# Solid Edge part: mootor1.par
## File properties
Author: Priit
Template: Normal.par
Last saved by: Priit
Revision: 7
Application: Solid Edge
Accuracy: 0,990
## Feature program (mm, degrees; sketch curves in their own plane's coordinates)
sketch for "unnamed Protrusion 1" plane through (0, 0, 0) normal (0, -1, 0) x-axis (1, 0, 0)
  circle centre (0, 0) radius 20
extrude "unnamed Protrusion 1" add finite 10 along -normal
sketch for "ExtrudedCutout_1" plane through (0, 0, 0) normal (0, -1, 0) x-axis (1, 0, 0)
  circle centre (0, 0) radius 15
extrude "ExtrudedCutout_1" cut finite 10 along -normal
fillet "Round_1" radius 5
sketch for "ExtrudedProtrusion_2" plane through (0, 0, 0) normal (1, 0, 0) x-axis (0, 1, 0)
  bspline degree 3 poles (2.6212, 20) (4.3488, 21.4343) (6.0292, 21.9791) (7.6625, 21.6343) knots 0 1 multiplicities 4 4
  line (6.3474, 18.5657) -> (7.6625, 21.6343)
  line (2.1828, 18.5657) -> (6.3474, 18.5657)
  line (2.1828, 18.5657) -> (2.6212, 20)
extrude "ExtrudedProtrusion_2" add finite 1 symmetric
pattern "unnamed Pattern 1" of "ExtrudedProtrusion_2"
pattern "unnamed Pattern 2"
sketch for "unnamed RevolvedProtrusion 1" plane through (0, 0, 0) normal (1, 0, 0) x-axis (0, 1, 0)
  line (10, 20) -> (15, 25)
  line (15, 25) -> (15, 20)
  line (10, 16) -> (15, 20)
  line (10, 20) -> (10, 16)
revolve "unnamed RevolvedProtrusion 1" add finite 360 deg
fillet "Round_2" radius 1
sketch for "ExtrudedCutout_2" plane through (0, 0, 0) normal (0, -1, 0) x-axis (1, 0, 0)
  circle centre (4.5277, 21.9125) radius 1.5
extrude "ExtrudedCutout_2" cut finite 47.8304 along -normal
pattern "unnamed Pattern 3" of "ExtrudedCutout_2"
pattern "unnamed Pattern 4"
sketch for "unnamed RevolvedProtrusion 2" plane through (0, 0, 0) normal (1, 0, 0) x-axis (0, 1, 0)
  bspline degree 3 poles (15, 20.0806) (20.5422, 21.8303) (28.1354, 24.3213) (39.3794, 17.4669) (46.3407, 18.6419) (51.5323, 19.3065) knots 0 0.4261 0.6162 1 multiplicities 4 1 1 4
  line (51.5323, 19.3065) -> (60, 22.8871)
  line (60, 22.8871) -> (60, 30)
  bspline degree 3 poles (15, 25) (29.5109, 27.3678) (44.5109, 29.0345) (60, 30) knots 0 1 multiplicities 4 4
  line (15, 25) -> (15, 20.0806)
revolve "unnamed RevolvedProtrusion 2" add finite 360 deg
lofted cutout "unnamed LoftedCutout 1"
pattern "unnamed Pattern 5" of "unnamed LoftedCutout 1"
lofted cutout "unnamed LoftedCutout 2"
lofted cutout "unnamed LoftedCutout 3"
lofted cutout "unnamed LoftedCutout 4"
lofted cutout "unnamed LoftedCutout 5"
lofted cutout "unnamed LoftedCutout 6"
lofted cutout "unnamed LoftedCutout 7"
lofted cutout "unnamed LoftedCutout 8"
lofted cutout "unnamed LoftedCutout 9"
lofted cutout "unnamed LoftedCutout 10"
lofted cutout "unnamed LoftedCutout 11"
lofted cutout "unnamed LoftedCutout 12"
lofted cutout "unnamed LoftedCutout 13"
lofted cutout "unnamed LoftedCutout 14"
lofted cutout "unnamed LoftedCutout 15"
lofted cutout "unnamed LoftedCutout 16"
sketch for "unnamed RevolvedProtrusion 3" plane through (0, 0, 0) normal (1, 0, 0) x-axis (0, 1, 0)
  line (6.5, 0) -> (60.3036, 0)
  bspline degree 3 poles (59.1983, -0.9944) (52.8144, -0.6563) (42.9225, 0.2361) (32.3089, -3.267) (27.6433, -3.8883) knots 0 0.5486 1 multiplicities 4 1 4
  arc centre (26.7048, 0) radius 4 from (27.6433, -3.8883) to (26.7048, -4) cw
  bspline degree 3 poles (26.7048, -4) (20.9583, -4.5984) (15.4317, -3.5385) (9, -2.5) knots 0 1 multiplicities 4 4
revolve "unnamed RevolvedProtrusion 3" add finite 360 deg
lofted protrusion "unnamed LoftedProtrusion 1"
pattern "unnamed Pattern 6" of "unnamed LoftedProtrusion 1"
pattern "unnamed Pattern 7"
mirror "unnamed Mirror 1" of "unnamed Pattern 7", "unnamed LoftedProtrusion 1" about plane through (0, 15, 0) normal (0, -1, 0)
lofted protrusion "unnamed LoftedProtrusion 2"
pattern "unnamed Pattern 8" of "unnamed LoftedProtrusion 2"
mirror "unnamed Mirror 2" of "unnamed Pattern 7", "unnamed LoftedProtrusion 1" about plane through (0, 18.155, 0) normal (0, -1, 0)
lofted protrusion "unnamed LoftedProtrusion 3"
pattern "unnamed Pattern 9" of "unnamed LoftedProtrusion 3"
mirror "unnamed Mirror 3" of "unnamed Pattern 7", "unnamed LoftedProtrusion 1" about plane through (0, 22.0786, 0) normal (0, -1, 0)
lofted protrusion "unnamed LoftedProtrusion 4"
pattern "unnamed Pattern 10" of "unnamed LoftedProtrusion 4"
helix protrusion "HelixProtrusion_1"  Pitch = 5 mm
lofted protrusion "unnamed LoftedProtrusion 5"
sketch for "unnamed RevolvedCutout 1" plane through (0, 0, 0) normal (1, 0, 0) x-axis (0, 1, 0)
  line (132.0002, -1.25) -> (107.0002, -1.25)
  line (107.0002, -1.25) -> (107.0002, -24.2673)
  line (132.0002, -19.5296) -> (107.0002, -24.2673)
  line (132.0002, -19.5296) -> (132.0002, -1.25)
revolve "unnamed RevolvedCutout 1" cut finite 360 deg
sketch for "ExtrudedProtrusion_5" plane through (0, 0, 26.857) normal (0, 0, 1) x-axis (1, 0, 0)
  line (-2.4333, 48.7594) -> (1.5667, 48.7594)
  line (1.5667, 48.7594) -> (1.7399, 53.8575)
  line (1.7399, 53.8575) -> (0, 53.8575)
  line (0, 53.8575) -> (-2.4333, 53.8575)
  line (-2.4333, 53.8575) -> (-2.4333, 48.7594)
extrude "ExtrudedProtrusion_5" add finite 5.7761 along +normal
sketch for "ExtrudedProtrusion_6" plane through (0, 0, 26.857) normal (0, 0, 1) x-axis (1, 0, 0)
  line (-2, 110.9177) -> (-2, 117.1802)
  line (-2, 117.1802) -> (2, 117.1802)
  line (2, 117.1802) -> (2, 110.9177)
  line (2, 110.9177) -> (0, 110.9177)
  line (0, 110.9177) -> (-2, 110.9177)
extrude "ExtrudedProtrusion_6" add finite 6.8669 along +normal
draft "Draft_1"  Angles1 = 3 deg
draft "Draft_2"  Angles1 = 15 deg
sketch for "unnamed Protrusion 2" plane through (-0.3467, 53.8575, 31.0556) normal (0, 1, 0) x-axis (-1, 0, 0)
  circle centre (0.4773, 0.2486) radius 1.0664
extrude "unnamed Protrusion 2" add to key point along +normal
pattern "unnamed Pattern 11" of "unnamed Protrusion 2", "Draft_2", "ExtrudedProtrusion_5"
extrude "unnamed Protrusion 3" add finite 5.7761
draft "unnamed Draft 1"
extrude "unnamed Protrusion 4" add finite 57.0602
extrude "unnamed Protrusion 5" add finite 5.7761
draft "unnamed Draft 2"
extrude "unnamed Protrusion 6" add finite 57.0602
extrude "unnamed Protrusion 7" add finite 5.7761
draft "unnamed Draft 3"
extrude "unnamed Protrusion 8" add finite 57.0602
extrude "unnamed Protrusion 9" add finite 5.7761
draft "unnamed Draft 4"
extrude "unnamed Protrusion 10" add finite 57.0602
pattern "unnamed Pattern 12" of "ExtrudedProtrusion_6"
extrude "unnamed Protrusion 11" add finite 6.8669
extrude "unnamed Protrusion 12" add finite 6.8669
extrude "unnamed Protrusion 13" add finite 6.8669
extrude "unnamed Protrusion 14" add finite 6.8669
sketch for "ExtrudedProtrusion_23" plane through (22.1172, 0, 0) normal (1, 0, 0) x-axis (0, 1, 0)
  line (22.2131, 4.1624) -> (55.0053, 3.4731)
  line (55.0053, -3.4731) -> (22.2131, -4.1624)
extrude "ExtrudedProtrusion_23" add finite 11.2927 along +normal
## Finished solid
Body 1: solid body, 692 faces, 1912 edges, 1267 vertices, 2 separate solids.
  Faces by surface: spline 430, plane 204, cylinder 28, swept 16, cone 5, spun 4, sphere 3, torus 2
  Edges by curve: intersection 523, circle 494, spline 464, line 334, ellipse 49, curve on surface 48
Bounding box of the edges (mm; curved faces can reach further): 65.732 x 132.000 x 65.704, from (-32.3219, 0, -30) to (33.4099, 132.0002, 35.704).
Cylindrical faces by radius (mm): R1.0664 x5, R1.5 x16, R3.4731 x2, R4.1661 x3, R15 x1, R20 x1
Conical faces (half-angle, radius in mm at the cone's reference point): 10.7309 deg R23.0173 x1, 11.3099 deg R30 x1, 22.9214 deg R19.3065 x1, 38.6598 deg R20 x1, 45 deg R20 x1
Toroidal faces (ring radius, tube radius in mm): R16 r1 x1, R20 r5 x1
Spherical faces by radius (mm): R1 x1, R2.5 x1, R4 x1
Planar faces by outward normal: +x 5, +y 29, +z 7, -x 9, -y 27, -z 6, oblique 121
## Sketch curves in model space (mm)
line (22.1172, 22.2131, 4.1624) -> (22.1172, 55.0053, 3.4731)
arc centre (22.1172, 55.0053, 0) radius 3.4731 from (22.1172, 55.0053, 3.4731) through (22.1172, 58.4769, -0.1029) to (22.1172, 55.0053, -3.4731)
line (22.1172, 55.0053, -3.4731) -> (22.1172, 22.2131, -4.1624)
arc centre (22.1172, 22.038, 0) radius 4.1661 from (22.1172, 22.2131, -4.1624) through (22.1172, 17.8719, 0) to (22.1172, 22.2131, 4.1624)
circle centre (-0.824, 53.8575, 31.3042) radius 1.0664
line (-2, 110.9177, 26.857) -> (-2, 117.1802, 26.857)
line (-2, 117.1802, 26.857) -> (2, 117.1802, 26.857)
line (2, 117.1802, 26.857) -> (2, 110.9177, 26.857)
line (2, 110.9177, 26.857) -> (0, 110.9177, 26.857)
line (0, 110.9177, 26.857) -> (-2, 110.9177, 26.857)
line (-2.4333, 53.8575, 26.857) -> (-2.4333, 48.7594, 26.857)
line (-2.4333, 48.7594, 26.857) -> (1.5667, 48.7594, 26.857)
line (1.5667, 48.7594, 26.857) -> (1.7399, 53.8575, 26.857)
line (1.7399, 53.8575, 26.857) -> (0, 53.8575, 26.857)
line (0, 53.8575, 26.857) -> (-2.4333, 53.8575, 26.857)
line (0, 132.0002, -19.5296) -> (0, 107.0002, -24.2673)
line (0, 132.0002, -19.5296) -> (0, 132.0002, -1.25)
line (0, 132.0002, -1.25) -> (0, 107.0002, -1.25)
line (0, 107.0002, -1.25) -> (0, 107.0002, -24.2673)
circle centre (0, 132.0002, 0) radius 25
circle centre (0, 107.0002, 0) radius 30
line (1.5127, 11.6384, 16.857) -> (0.64, 11.2314, 16.857)
line (0.64, 11.2314, 16.857) -> (-1.9156, 13.43, 16.857)
line (-1.9156, 13.43, 16.857) -> (-1.0024, 13.7955, 16.857)
line (-1.0024, 13.7955, 16.857) -> (1.5127, 11.6384, 16.857)
line (1.9309, 10.121, 10.8124) -> (2.257, 11, 10.8124)
line (2.257, 11, 10.8124) -> (-1.8142, 14.4918, 10.8124)
line (-2.2025, 13.6767, 10.8124) -> (-1.8142, 14.4918, 10.8124)
line (-2.2025, 13.6767, 10.8124) -> (1.9309, 10.121, 10.8124)
line (1.9102, 11.0151, 5.5392) -> (2.257, 11.8754, 5.5392)
line (1.9102, 11.0151, 5.5392) -> (-2.2025, 12.6728, 5.5392)
line (-1.8558, 13.533, 5.5392) -> (-2.2025, 12.6728, 5.5392)
line (-1.8558, 13.533, 5.5392) -> (2.257, 11.8754, 5.5392)
line (1.2832, 11.8442, 0) -> (0.5347, 11.3475, 0)
line (0.5347, 11.3475, 0) -> (-1.583, 12.9479, 0)
line (-1.583, 12.9479, 0) -> (-0.67, 13.1549, 0)
line (-0.67, 13.1549, 0) -> (1.2832, 11.8442, 0)
arc centre (0, 26.7048, 0) radius 4 from (0, 27.6433, -3.8883) through (0, 27.1774, -3.972) to (0, 26.7048, -4)
spline (0, 26.7048, -4) -> (0, 18.1094, -3.8638) -> (0, 9, -2.5)
arc centre (0, 9, 0) radius 2.5 from (0, 9, -2.5) through (0, 7.1816, -1.7156) to (0, 6.5, 0)
line (0, 6.5, 0) -> (0, 60.3036, 0)
arc centre (0, 59.3036, 0) radius 1 from (0, 60.3036, 0) through (0, 59.9725, -0.7434) to (0, 59.1983, -0.9944)
spline (0, 59.1983, -0.9944) -> (0, 43.2394, -0.8087) -> (0, 27.6433, -3.8883)
arc centre (-0.614, 51.5323, 16.857) radius 1 from (-0.7188, 50.5378, 16.857) through (-1.6126, 51.5847, 16.857) to (-0.614, 52.5323, 16.857)
line (1.3114, 50.1421, 16.857) -> (-0.7188, 50.5378, 16.857)
arc centre (1.8747, 51.5323, 16.857) radius 1.5 from (2.311, 50.0971, 16.857) through (1.8073, 50.0338, 16.857) to (1.3114, 50.1421, 16.857)
line (4.3476, 50.3998, 16.857) -> (2.311, 50.0971, 16.857)
arc centre (4.3476, 51.3998, 16.857) radius 1 from (4.3476, 52.3998, 16.857) through (5.3472, 51.3702, 16.857) to (4.3476, 50.3998, 16.857)
line (2.5948, 52.8481, 16.857) -> (4.3476, 52.3998, 16.857)
arc centre (1.8747, 51.5323, 16.857) radius 1.5 from (1.2953, 52.9159, 16.857) through (1.9528, 53.0302, 16.857) to (2.5948, 52.8481, 16.857)
line (1.2953, 52.9159, 16.857) -> (-0.614, 52.5323, 16.857)
line (2.8775, 44.7892, 25.1125) -> (5.5693, 44.7892, 23.9277)
arc centre (5.2693, 44.7892, 22.9738) radius 1 from (5.5693, 44.7892, 23.9277) through (6.2406, 44.7892, 22.7361) to (5.2122, 44.7892, 21.9754)
line (5.2122, 44.7892, 21.9754) -> (2.7667, 44.7892, 22.1151)
line (2.7667, 44.7892, 22.1151) -> (0.3139, 44.7892, 23.1586)
arc centre (0.4116, 44.7892, 24.1538) radius 1 from (0.3139, 44.7892, 23.1586) through (-0.5817, 44.7892, 24.2697) to (0.4284, 44.7892, 25.1537)
line (0.4284, 44.7892, 25.1537) -> (2.8775, 44.7892, 25.1125)
line (5.4591, 33.232, 25.9297) -> (7.9268, 33.232, 24.6584)
arc centre (7.6105, 33.232, 23.7097) radius 1 from (7.9268, 33.232, 24.6584) through (8.5744, 33.232, 23.4432) to (7.512, 33.232, 22.7146)
line (7.512, 33.232, 22.7146) -> (5.0733, 33.232, 22.956)
line (5.0733, 33.232, 22.956) -> (2.7356, 33.232, 24.3419)
arc centre (2.8847, 33.232, 25.3307) radius 1 from (2.7356, 33.232, 24.3419) through (1.9016, 33.232, 25.5139) to (3.0434, 33.232, 26.318)
line (3.0434, 33.232, 26.318) -> (5.4591, 33.232, 25.9297)
arc centre (5.5835, 26.7048, 24.7206) radius 1 from (5.784, 26.7048, 25.7003) through (5.9932, 26.7048, 25.6328) to (6.1826, 26.7048, 25.5213)
line (6.1826, 26.7048, 25.5213) -> (7.3775, 26.7048, 24.9847)
arc centre (7.2671, 26.7048, 24.2429) radius 0.75 from (7.3775, 26.7048, 24.9847) through (7.9914, 26.7048, 24.0482) to (7.0749, 26.7048, 23.5179)
line (7.0749, 26.7048, 23.5179) -> (5.4702, 26.7048, 23.727)
line (5.4702, 26.7048, 23.727) -> (3.8083, 26.7048, 24.5736)
arc centre (3.9517, 26.7048, 25.3097) radius 0.75 from (3.8083, 26.7048, 24.5736) through (3.2209, 26.7048, 25.4784) to (4.102, 26.7048, 26.0445)
line (4.102, 26.7048, 26.0445) -> (5.784, 26.7048, 25.7003)
circle centre (4.4932, 15, 21.9294) radius 1.5
line (0, 15, 0) -> (0, 60, 0)
spline (0, 15, 20.0806) -> (0, 33.2698, 21.0714) -> (0, 51.5323, 19.3065)
line (0, 51.5323, 19.3065) -> (0, 60, 22.8871)
line (0, 60, 22.8871) -> (0, 60, 30)
spline (0, 15, 25) -> (0, 37.1332, 28.0259) -> (0, 60, 30)
line (0, 15, 25) -> (0, 15, 20.0806)
circle centre (4.5277, 0, 21.9125) radius 1.5
line (0, 9.2079, 0) -> (0, 15.9588, 0)
line (0, 15, 25) -> (0, 15, 20)
line (0, 10, 16) -> (0, 15, 20)
line (0, 10, 20) -> (0, 10, 16)
line (0, 10, 20) -> (0, 15, 25)
circle centre (0, 15, 0) radius 25
circle centre (0, 15, 0) radius 25
circle centre (0, 10, 0) radius 20
line (0, 6.3474, 18.5657) -> (0, 7.6625, 21.6343)
spline (0, 2.6212, 20) -> (0, 5.1772, 21.4843) -> (0, 7.6625, 21.6343)
line (0, 2.1828, 18.5657) -> (0, 2.6212, 20)
line (0, 2.1828, 18.5657) -> (0, 6.3474, 18.5657)
circle centre (0, 0, 0) radius 15
circle centre (0, 0, 0) radius 20
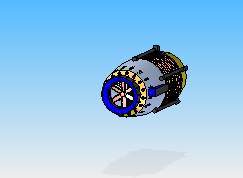
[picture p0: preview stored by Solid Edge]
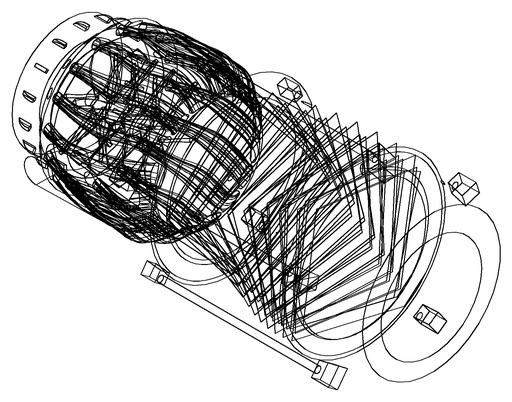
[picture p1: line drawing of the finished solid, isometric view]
